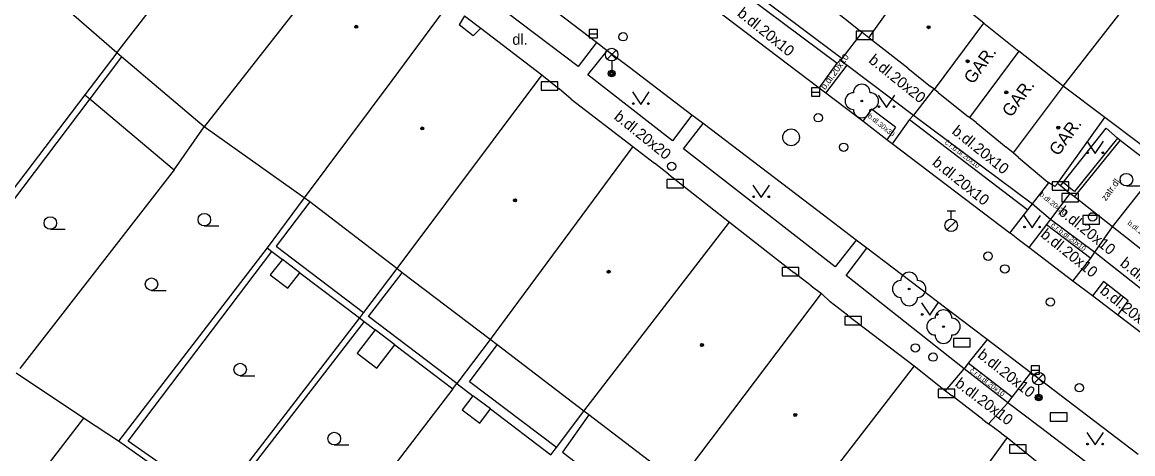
# Model space of a CAD drawing. Extents: x -595546 to -593986, y -1160845 to -1159202.
# Drawn here: x -595188.5 to -595122.2, y -1160653.2 to -1160627.4 of the extents above; entities that cross this region are included whole.
import ezdxf

# ---------------------------------------------------------------- set-up
doc = ezdxf.new("R2010")
doc.units = 0
for name, color, linetype in [('DOP - kresba z DSPS bez souradnic', 7, 'Continuous'), ('DOP - rozhrani ploch obecne', 7, 'Continuous'), ('Level 22', 7, 'Continuous'), ('Level 24', 7, 'Continuous'), ('Level 27', 7, 'Continuous'), ('Level 28', 7, 'Continuous'), ('Level 33', 7, 'Continuous'), ('Level 36', 7, 'Continuous'), ('Level 39', 7, 'Continuous'), ('TM - budovy zdene_ betonove - NP', 7, 'Continuous'), ('TM - budovy zdene_ betonove - VP', 7, 'Continuous'), ('TM - chodniky - VP', 7, 'Continuous'), ('TM - komunikace - VP', 7, 'Continuous'), ('TM - podezdivka plotu - VP', 7, 'Continuous'), ('TM - popis objektu', 7, 'Continuous'), ('TM - popis povrchu', 7, 'Continuous'), ('TM - rozhrani mezi zpev. plochami mezi sebou - VP', 7, 'Continuous'), ('TM - rozhrani ploch obecne - VP', 7, 'Continuous'), ('TM - vstup do budovy - zdene_ betonove', 7, 'Continuous'), ('TM - vstup do budovy - zdene_ betonove  - shora neviditelny', 7, 'Continuous'), ('TM - zed operna - VP', 7, 'Continuous')]:
    doc.layers.add(name, color=color, linetype=linetype)

msp = doc.modelspace()

# ---------------------------------------------------------------- linework, layer by layer
at = {"layer": 'DOP - kresba z DSPS bez souradnic'}
for points in [[(-595182.53, -1160629.5), (-595184.42, -1160632)], [(-595184.42, -1160632), (-595193.73, -1160644.32)], [(-595171.29, -1160638.17), (-595173.3, -1160640.82)], [(-595182.14, -1160652.47), (-595173.55, -1160641.13)], [(-595173.3, -1160640.82), (-595168.08, -1160644.78)], [(-595171.88, -1160642.4), (-595172.92, -1160641.61)], [(-595167.78, -1160645.02), (-595165.77, -1160642.4)], [(-595168.05, -1160645.31), (-595176.58, -1160656.37)], [(-595162.51, -1160649.02), (-595167.78, -1160645.02)], [(-595166.21, -1160646.71), (-595167.38, -1160645.82)], [(-595161.75, -1160648.91), (-595160.11, -1160646.71)], [(-595156.57, -1160652.85), (-595161.75, -1160648.91)], [(-595160.51, -1160650.54), (-595161.55, -1160649.75)], [(-595154.64, -1160650.9), (-595156.21, -1160653.12)], [(-595176.85, -1160656.17), (-595182.14, -1160652.47)], [(-595156.21, -1160653.12), (-595151.19, -1160656.94)]]:
    msp.add_lwpolyline(points, dxfattribs=at)
at = {"layer": 'DOP - rozhrani ploch obecne'}
for points in [[(-595182.82, -1160629.25), (-595184.73, -1160631.77)], [(-595184.73, -1160631.77), (-595194.24, -1160644.28)], [(-595184.73, -1160631.77), (-595184.42, -1160632)], [(-595184.42, -1160632), (-595179.38, -1160636.26)], [(-595179.38, -1160636.26), (-595177.6, -1160633.68)], [(-595179.38, -1160636.26), (-595188.61, -1160648.13)], [(-595171.62, -1160637.92), (-595173.84, -1160640.91)], [(-595173.84, -1160640.91), (-595182.72, -1160652.47)], [(-595173.84, -1160640.91), (-595173.55, -1160641.13)], [(-595173.55, -1160641.13), (-595172.92, -1160641.61)], [(-595172.92, -1160641.61), (-595173.65, -1160642.53)], [(-595173.65, -1160642.53), (-595172.61, -1160643.32)], [(-595172.61, -1160643.32), (-595171.88, -1160642.4)], [(-595171.88, -1160642.4), (-595168.33, -1160645.1)], [(-595166.1, -1160642.14), (-595168.08, -1160644.78)], [(-595168.33, -1160645.1), (-595176.85, -1160656.17)], [(-595168.08, -1160644.78), (-595168.33, -1160645.1)], [(-595168.33, -1160645.1), (-595168.05, -1160645.31)], [(-595168.05, -1160645.31), (-595167.38, -1160645.82)], [(-595167.38, -1160645.82), (-595168.47, -1160647.21)], [(-595167.29, -1160648.1), (-595166.21, -1160646.71)], [(-595166.21, -1160646.71), (-595162.76, -1160649.34)], [(-595160.53, -1160646.39), (-595162.51, -1160649.02)], [(-595168.47, -1160647.21), (-595167.29, -1160648.1)], [(-595184.8, -1160651.08), (-595188.82, -1160648.4)], [(-595162.76, -1160649.34), (-595171.1, -1160660.23)], [(-595162.76, -1160649.34), (-595162.51, -1160649.02)], [(-595162.51, -1160649.02), (-595161.55, -1160649.75)], [(-595161.55, -1160649.75), (-595162.19, -1160650.6)], [(-595162.19, -1160650.6), (-595161.15, -1160651.39)], [(-595161.15, -1160651.39), (-595160.51, -1160650.54)], [(-595160.51, -1160650.54), (-595156.91, -1160653.28)], [(-595156.57, -1160652.85), (-595154.93, -1160650.67)], [(-595184.8, -1160651.08), (-595190.54, -1160658.52)], [(-595182.72, -1160652.47), (-595184.8, -1160651.08)], [(-595178.89, -1160655.17), (-595182.72, -1160652.47)], [(-595156.91, -1160653.28), (-595156.57, -1160652.85)]]:
    msp.add_lwpolyline(points, dxfattribs=at)
at = {"layer": 'Level 22'}
for centre in [(-595138.34, -1160632.14), (-595135.51, -1160643.37), (-595133.46, -1160645.62)]:
    msp.add_circle(centre, 0.05, dxfattribs=at)
for centre, start, end in [((-595138.34, -1160631.64), 0, 180), ((-595138.84, -1160632.14), 90, 270), ((-595137.84, -1160632.14), 270, 90), ((-595138.34, -1160632.64), 180, 0), ((-595135.51, -1160642.87), 0, 180), ((-595136.01, -1160643.37), 90, 270), ((-595135.01, -1160643.37), 270, 90), ((-595135.51, -1160643.87), 180, 0), ((-595133.46, -1160645.12), 0, 180), ((-595133.96, -1160645.62), 90, 270), ((-595132.96, -1160645.62), 270, 90), ((-595133.46, -1160646.12), 180, 0)]:
    msp.add_arc(centre, 0.5, start, end, dxfattribs=at)
at = {"layer": 'Level 24'}
for points in [[(-595138.668, -1160628.469), (-595137.668, -1160628.469), (-595137.668, -1160627.969), (-595138.668, -1160627.969)], [(-595157.478, -1160631.489), (-595156.478, -1160631.489), (-595156.478, -1160630.989), (-595157.478, -1160630.989)], [(-595149.978, -1160637.319), (-595148.978, -1160637.319), (-595148.978, -1160636.819), (-595149.978, -1160636.819)], [(-595126.977, -1160637.458), (-595125.977, -1160637.458), (-595125.977, -1160636.958), (-595126.977, -1160636.958)], [(-595126.397, -1160638.168), (-595125.397, -1160638.168), (-595125.397, -1160637.668), (-595126.397, -1160637.668)], [(-595125.138, -1160639.489), (-595124.138, -1160639.489), (-595124.138, -1160638.989), (-595125.138, -1160638.989)], [(-595143.098, -1160642.579), (-595142.098, -1160642.579), (-595142.098, -1160642.079), (-595143.098, -1160642.079)], [(-595139.348, -1160645.509), (-595138.348, -1160645.509), (-595138.348, -1160645.009), (-595139.348, -1160645.009)], [(-595132.867, -1160646.828), (-595131.867, -1160646.828), (-595131.867, -1160646.328), (-595132.867, -1160646.328)], [(-595133.788, -1160649.849), (-595132.788, -1160649.849), (-595132.788, -1160649.349), (-595133.788, -1160649.349)], [(-595127.087, -1160651.278), (-595126.087, -1160651.278), (-595126.087, -1160650.778), (-595127.087, -1160650.778)], [(-595129.528, -1160653.179), (-595128.528, -1160653.179), (-595128.528, -1160652.679), (-595129.528, -1160652.679)]]:
    msp.add_lwpolyline(points, close=True, dxfattribs=at)
at = {"layer": 'Level 27'}
for p, q in [((-595154.61, -1160628.12), (-595154.11, -1160628.12)), ((-595141.35, -1160631.6), (-595140.85, -1160631.6)), ((-595128.22, -1160648.22), (-595127.72, -1160648.22))]:
    msp.add_line(p, q, dxfattribs=at)
for points in [[(-595154.61, -1160628.37), (-595154.11, -1160628.37), (-595154.11, -1160627.87), (-595154.61, -1160627.87)], [(-595141.35, -1160631.85), (-595140.85, -1160631.85), (-595140.85, -1160631.35), (-595141.35, -1160631.35)], [(-595128.22, -1160648.47), (-595127.72, -1160648.47), (-595127.72, -1160647.97), (-595128.22, -1160647.97)]]:
    msp.add_lwpolyline(points, close=True, dxfattribs=at)
msp.add_circle((-595142.56, -1160634.31), 0.5, dxfattribs=at)
at = {"layer": 'Level 28'}
for p, q in [((-595133.25, -1160638.695), (-595132.75, -1160638.695)), ((-595133, -1160639.195), (-595133, -1160638.695)), ((-595133.258, -1160639.842), (-595132.728, -1160639.312))]:
    msp.add_line(p, q, dxfattribs=at)
for centre, radius in [((-595152.59, -1160628.3), 0.25), ((-595140.94, -1160633.14), 0.25), ((-595139.42, -1160634.9), 0.25), ((-595149.69, -1160636.04), 0.25), ((-595133, -1160639.57), 0.375), ((-595124.56, -1160639.06), 0.25), ((-595130.8, -1160641.41), 0.25), ((-595129.8, -1160642.17), 0.25), ((-595127.08, -1160644.15), 0.25), ((-595135.14, -1160646.89), 0.25), ((-595134.08, -1160647.44), 0.25), ((-595125.35, -1160649.27), 0.25)]:
    msp.add_circle(centre, radius, dxfattribs=at)
at = {"layer": 'Level 33'}
for p, q in [((-595153.535, -1160629.63), (-595153.005, -1160629.1)), ((-595153.535, -1160629.1), (-595153.005, -1160629.63)), ((-595153.27, -1160629.74), (-595153.27, -1160630.49)), ((-595128.045, -1160648.99), (-595127.515, -1160648.46)), ((-595128.045, -1160648.46), (-595127.515, -1160648.99)), ((-595127.78, -1160649.1), (-595127.78, -1160649.85))]:
    msp.add_line(p, q, dxfattribs=at)
for centre, radius in [((-595153.27, -1160629.365), 0.375), ((-595153.27, -1160630.49), 0.2), ((-595153.27, -1160630.49), 0.145), ((-595153.27, -1160630.49), 0.0876), ((-595127.78, -1160648.725), 0.375), ((-595127.78, -1160649.85), 0.2), ((-595127.78, -1160649.85), 0.145), ((-595127.78, -1160649.85), 0.0876)]:
    msp.add_circle(centre, radius, dxfattribs=at)
at = {"layer": 'Level 36'}
for p, q in [((-595122.54, -1160637.215), (-595121.665, -1160637.215)), ((-595186.78, -1160639.805), (-595185.905, -1160639.805)), ((-595177.59, -1160639.605), (-595176.715, -1160639.605)), ((-595180.74, -1160643.455), (-595179.865, -1160643.455)), ((-595175.45, -1160648.555), (-595174.575, -1160648.555)), ((-595169.83, -1160652.685), (-595168.955, -1160652.685))]:
    msp.add_line(p, q, dxfattribs=at)
for points in [[(-595152.03, -1160631.59), (-595151.53, -1160632.34), (-595151.03, -1160631.59)], [(-595137.36, -1160631.78), (-595136.86, -1160632.53), (-595136.36, -1160631.78)], [(-595124.9, -1160634.53), (-595124.4, -1160635.28), (-595123.9, -1160634.53)], [(-595144.84, -1160637.16), (-595144.34, -1160637.91), (-595143.84, -1160637.16)], [(-595128.67, -1160638.97), (-595128.17, -1160639.72), (-595127.67, -1160638.97)], [(-595134.78, -1160644.19), (-595134.28, -1160644.94), (-595133.78, -1160644.19)], [(-595124.91, -1160651.94), (-595124.41, -1160652.69), (-595123.91, -1160651.94)]]:
    msp.add_lwpolyline(points, dxfattribs=at)
for centre, radius in [((-595151.98, -1160632.29), 0.05), ((-595151.081, -1160632.29), 0.05), ((-595137.31, -1160632.48), 0.05), ((-595136.411, -1160632.48), 0.05), ((-595124.85, -1160635.23), 0.05), ((-595123.951, -1160635.23), 0.05), ((-595122.54, -1160636.84), 0.375), ((-595144.79, -1160637.86), 0.05), ((-595143.891, -1160637.86), 0.05), ((-595186.78, -1160639.43), 0.375), ((-595177.59, -1160639.23), 0.375), ((-595128.62, -1160639.67), 0.05), ((-595127.721, -1160639.67), 0.05), ((-595180.74, -1160643.08), 0.375), ((-595134.73, -1160644.89), 0.05), ((-595133.831, -1160644.89), 0.05), ((-595175.45, -1160648.18), 0.375), ((-595169.83, -1160652.31), 0.375), ((-595124.86, -1160652.64), 0.05), ((-595123.961, -1160652.64), 0.05)]:
    msp.add_circle(centre, radius, dxfattribs=at)
at = {"layer": 'Level 39'}
for centre, radius in [((-595168.52, -1160627.7), 0.09), ((-595168.52, -1160627.7), 0.0398), ((-595134.35, -1160627.73), 0.09), ((-595134.35, -1160627.73), 0.0398), ((-595132.02, -1160629.76), 0.09), ((-595132.02, -1160629.76), 0.0398), ((-595129.71, -1160631.62), 0.09), ((-595129.71, -1160631.62), 0.0398), ((-595164.58, -1160633.78), 0.09), ((-595164.58, -1160633.78), 0.0398), ((-595126.61, -1160633.73), 0.09), ((-595126.61, -1160633.73), 0.0398), ((-595159.04, -1160638.07), 0.09), ((-595159.04, -1160638.07), 0.0398), ((-595153.45, -1160642.34), 0.09), ((-595153.45, -1160642.34), 0.0398), ((-595147.88, -1160646.72), 0.09), ((-595147.88, -1160646.72), 0.0398), ((-595142.31, -1160650.9), 0.09), ((-595142.31, -1160650.9), 0.0398)]:
    msp.add_circle(centre, radius, dxfattribs=at)
at = {"layer": 'TM - budovy zdene_ betonove - NP'}
for points in [[(-595137.92, -1160628.36), (-595135.04, -1160624.3)], [(-595162.05, -1160627.04), (-595162.38, -1160627.59)], [(-595161.54, -1160628.24), (-595161.08, -1160627.78)]]:
    msp.add_lwpolyline(points, dxfattribs=at)
at = {"layer": 'TM - budovy zdene_ betonove - VP'}
for points in [[(-595182.82, -1160629.25), (-595173.99, -1160617.88)], [(-595126.32, -1160631.26), (-595118.68, -1160621.44)], [(-595182.82, -1160629.25), (-595189.46, -1160623.47)], [(-595131.06, -1160627.48), (-595135.04, -1160624.3)], [(-595162.99, -1160626.32), (-595166.4, -1160630.91)], [(-595172.23, -1160626.83), (-595177.6, -1160633.68)], [(-595162.05, -1160627.04), (-595161.08, -1160627.78)], [(-595133.99, -1160631.46), (-595131.06, -1160627.48)], [(-595131.06, -1160627.48), (-595128.97, -1160629.15)], [(-595161.08, -1160627.78), (-595157.43, -1160630.57)], [(-595138.31, -1160628.05), (-595138.44, -1160627.95)], [(-595137.92, -1160628.36), (-595138.31, -1160628.05)], [(-595135.59, -1160630.18), (-595137.92, -1160628.36)], [(-595182.53, -1160629.5), (-595182.82, -1160629.25)], [(-595128.97, -1160629.15), (-595131.91, -1160633.13)], [(-595126.32, -1160631.26), (-595128.97, -1160629.15)], [(-595177.6, -1160633.68), (-595182.53, -1160629.5)], [(-595157.43, -1160630.57), (-595166.1, -1160642.14)], [(-595157.43, -1160630.57), (-595156.41, -1160631.42)], [(-595166.4, -1160630.91), (-595171.62, -1160637.92)], [(-595134.04, -1160631.42), (-595134.24, -1160631.27)], [(-595133.99, -1160631.46), (-595134.04, -1160631.42)], [(-595133.78, -1160631.63), (-595133.99, -1160631.46)], [(-595126.32, -1160631.26), (-595129.31, -1160635.23)], [(-595123.83, -1160633.13), (-595126.32, -1160631.26)], [(-595155.68, -1160632.02), (-595152, -1160634.86)], [(-595131.91, -1160633.13), (-595131.97, -1160633.08)], [(-595131.52, -1160633.43), (-595131.91, -1160633.13)], [(-595126.66, -1160637.06), (-595123.83, -1160633.13)], [(-595119.49, -1160636.39), (-595123.83, -1160633.13)], [(-595171.62, -1160637.92), (-595177.6, -1160633.68)], [(-595152, -1160634.86), (-595160.53, -1160646.39)], [(-595152, -1160634.86), (-595150.72, -1160635.86)], [(-595129.31, -1160635.23), (-595129.71, -1160634.9)], [(-595128.98, -1160635.51), (-595129.31, -1160635.23)], [(-595149.88, -1160636.51), (-595146.23, -1160639.37)], [(-595127.17, -1160637.02), (-595127.23, -1160636.98)], [(-595126.81, -1160637.25), (-595127.17, -1160637.02)], [(-595126.66, -1160637.06), (-595126.81, -1160637.25)], [(-595171.29, -1160638.17), (-595171.62, -1160637.92)], [(-595166.1, -1160642.14), (-595171.29, -1160638.17)], [(-595154.93, -1160650.67), (-595146.23, -1160639.37)], [(-595146.23, -1160639.37), (-595142.4, -1160642.38)], [(-595165.77, -1160642.4), (-595166.1, -1160642.14)], [(-595160.53, -1160646.39), (-595165.77, -1160642.4)], [(-595141.37, -1160643.18), (-595140.75, -1160643.64)], [(-595149.3, -1160654.98), (-595140.75, -1160643.64)], [(-595140.75, -1160643.64), (-595140.22, -1160644.13)], [(-595139.19, -1160644.93), (-595135.22, -1160647.97)], [(-595160.11, -1160646.71), (-595160.53, -1160646.39)], [(-595154.93, -1160650.67), (-595160.11, -1160646.71)], [(-595135.22, -1160647.97), (-595143.84, -1160659.15)], [(-595135.22, -1160647.97), (-595133.34, -1160649.45)], [(-595133.34, -1160649.45), (-595132.95, -1160649.76)], [(-595154.64, -1160650.9), (-595154.93, -1160650.67)], [(-595149.58, -1160654.76), (-595154.64, -1160650.9)], [(-595131.11, -1160651.17), (-595130.77, -1160651.43)], [(-595130.01, -1160651.98), (-595129.65, -1160652.25)], [(-595129.65, -1160652.25), (-595135.63, -1160660.49)], [(-595129.65, -1160652.25), (-595124.5, -1160656.42)]]:
    msp.add_lwpolyline(points, dxfattribs=at)
at = {"layer": 'TM - chodniky - VP'}
for points in [[(-595155.28, -1160630.08), (-595162.12, -1160624.88)], [(-595154.17, -1160628.64), (-595155.28, -1160630.08)], [(-595154.69, -1160630.57), (-595153.53, -1160629.13)], [(-595140.48, -1160631.67), (-595139.22, -1160630)], [(-595139.22, -1160630), (-595135.25, -1160632.98)], [(-595149.64, -1160634.51), (-595154.69, -1160630.57)], [(-595137.75, -1160632.62), (-595138.27, -1160633.35)], [(-595136.32, -1160633.71), (-595137.75, -1160632.62)], [(-595148.48, -1160632.98), (-595149.64, -1160634.51)], [(-595135.49, -1160633.25), (-595136.53, -1160634.69)], [(-595135.25, -1160632.98), (-595135.49, -1160633.25)], [(-595148.98, -1160634.99), (-595147.81, -1160633.49)], [(-595136.32, -1160633.71), (-595136.84, -1160634.45)], [(-595139.93, -1160642.05), (-595148.98, -1160634.99)], [(-595123.37, -1160639.66), (-595125.63, -1160637.86)], [(-595129.5, -1160640.03), (-595128.42, -1160638.64)], [(-595128.42, -1160638.64), (-595128.14, -1160638.29)], [(-595128.14, -1160638.29), (-595127.07, -1160639.19)], [(-595127.07, -1160639.19), (-595127.32, -1160639.51)], [(-595127.32, -1160639.51), (-595128.36, -1160640.89)], [(-595121.38, -1160641.24), (-595122.53, -1160640.31), (-595123.37, -1160639.66)], [(-595138.67, -1160640.45), (-595139.93, -1160642.05)], [(-595139.27, -1160642.57), (-595138.03, -1160640.94)], [(-595124.67, -1160641.52), (-595124.43, -1160641.18)], [(-595124.43, -1160641.18), (-595118.95, -1160645.49)], [(-595125.73, -1160642.9), (-595124.67, -1160641.52)], [(-595132.22, -1160648.14), (-595139.27, -1160642.57)], [(-595123.9, -1160642.92), (-595124.56, -1160643.77)], [(-595122.43, -1160644.07), (-595123.9, -1160642.92)], [(-595123.05, -1160644.93), (-595122.43, -1160644.07)], [(-595130.85, -1160646.39), (-595131.98, -1160647.81)], [(-595131.98, -1160647.81), (-595132.22, -1160648.14)], [(-595129.36, -1160649.84), (-595128.24, -1160648.39)], [(-595129.62, -1160650.17), (-595129.36, -1160649.84)], [(-595127.75, -1160651.58), (-595129.62, -1160650.17)], [(-595123.26, -1160655.01), (-595127.75, -1160651.58)]]:
    msp.add_lwpolyline(points, dxfattribs=at)
at = {"layer": 'TM - komunikace - VP'}
for points in [[(-595154.17, -1160628.64), (-595160.08, -1160624.13)], [(-595140.88, -1160631.37), (-595148.28, -1160625.73)], [(-595153.53, -1160629.13), (-595154.17, -1160628.64)], [(-595152.21, -1160630.14), (-595153.53, -1160629.13)], [(-595148.48, -1160632.98), (-595152.21, -1160630.14)], [(-595140.48, -1160631.67), (-595140.88, -1160631.37)], [(-595139.99, -1160632.04), (-595140.48, -1160631.67)], [(-595138.27, -1160633.35), (-595139.99, -1160632.04)], [(-595147.81, -1160633.49), (-595148.48, -1160632.98)], [(-595137.38, -1160634.03), (-595138.27, -1160633.35)], [(-595140.96, -1160638.71), (-595147.81, -1160633.49)], [(-595136.84, -1160634.45), (-595137.38, -1160634.03)], [(-595136.53, -1160634.69), (-595136.84, -1160634.45)], [(-595129.5, -1160640.03), (-595136.53, -1160634.69)], [(-595138.67, -1160640.45), (-595140.96, -1160638.71)], [(-595129.43, -1160640.08), (-595129.5, -1160640.03)], [(-595128.92, -1160640.47), (-595129.43, -1160640.08)], [(-595138.03, -1160640.94), (-595138.67, -1160640.45)], [(-595128.36, -1160640.89), (-595128.92, -1160640.47)], [(-595131.74, -1160645.72), (-595138.03, -1160640.94)], [(-595125.73, -1160642.9), (-595128.36, -1160640.89)], [(-595124.56, -1160643.77), (-595125.73, -1160642.9)], [(-595123.05, -1160644.93), (-595124.56, -1160643.77)], [(-595121.06, -1160646.44), (-595123.05, -1160644.93)], [(-595130.85, -1160646.39), (-595131.74, -1160645.72)], [(-595128.24, -1160648.39), (-595130.85, -1160646.39)], [(-595127.35, -1160649.06), (-595128.24, -1160648.39)], [(-595121.84, -1160653.26), (-595127.35, -1160649.06)]]:
    msp.add_lwpolyline(points, dxfattribs=at)
at = {"layer": 'TM - podezdivka plotu - VP'}
for points in [[(-595125.63, -1160637.86), (-595122.92, -1160634.5)], [(-595126.48, -1160637.21), (-595126.66, -1160637.06)], [(-595125.91, -1160637.67), (-595126.48, -1160637.21)], [(-595125.63, -1160637.86), (-595125.91, -1160637.67)]]:
    msp.add_lwpolyline(points, dxfattribs=at)
at = {"layer": 'TM - rozhrani mezi zpev. plochami mezi sebou - VP'}
for points in [[(-595146.98, -1160623.98), (-595139.51, -1160629.59)], [(-595147.23, -1160624.32), (-595139.8, -1160629.88)], [(-595139.51, -1160629.59), (-595138.31, -1160628.05)], [(-595140.88, -1160631.37), (-595139.8, -1160629.88)], [(-595139.8, -1160629.88), (-595139.62, -1160629.7)], [(-595139.62, -1160629.7), (-595139.51, -1160629.59)], [(-595139.62, -1160629.7), (-595139.22, -1160630)], [(-595134.04, -1160631.42), (-595135.25, -1160632.98)], [(-595135.49, -1160633.25), (-595128.42, -1160638.64)], [(-595135.25, -1160632.98), (-595128.14, -1160638.29)], [(-595123.37, -1160639.66), (-595120.66, -1160636.23)], [(-595128.14, -1160638.29), (-595127.17, -1160637.02)], [(-595125.91, -1160637.67), (-595127.07, -1160639.19)], [(-595127.07, -1160639.19), (-595124.43, -1160641.18)], [(-595127.32, -1160639.51), (-595124.67, -1160641.52)], [(-595124.43, -1160641.18), (-595123.37, -1160639.66)], [(-595129.36, -1160649.84), (-595131.98, -1160647.81)], [(-595133.34, -1160649.45), (-595132.22, -1160648.14)], [(-595129.62, -1160650.17), (-595132.22, -1160648.14)], [(-595130.77, -1160651.43), (-595129.62, -1160650.17)]]:
    msp.add_lwpolyline(points, dxfattribs=at)
at = {"layer": 'TM - rozhrani ploch obecne - VP'}
for points in [[(-595126.32, -1160637.01), (-595123.74, -1160633.76)], [(-595123.07, -1160634.36), (-595123.74, -1160633.76)], [(-595122.92, -1160634.5), (-595123.07, -1160634.36)], [(-595120.66, -1160636.23), (-595122.92, -1160634.5)], [(-595126.48, -1160637.21), (-595126.32, -1160637.01)]]:
    msp.add_lwpolyline(points, dxfattribs=at)
at = {"layer": 'TM - vstup do budovy - zdene_ betonove'}
for points in [[(-595140.28, -1160626.48), (-595138.44, -1160627.95)], [(-595135.59, -1160630.18), (-595134.24, -1160631.27)], [(-595155.68, -1160632.02), (-595156.41, -1160631.42)], [(-595133.78, -1160631.63), (-595131.97, -1160633.08)], [(-595131.52, -1160633.43), (-595129.71, -1160634.9)], [(-595149.88, -1160636.51), (-595150.72, -1160635.86)], [(-595128.98, -1160635.51), (-595127.23, -1160636.98)], [(-595141.37, -1160643.18), (-595142.4, -1160642.38)], [(-595139.19, -1160644.93), (-595140.22, -1160644.13)], [(-595131.11, -1160651.17), (-595132.95, -1160649.76)], [(-595130.01, -1160651.98), (-595130.77, -1160651.43)]]:
    msp.add_lwpolyline(points, dxfattribs=at)
at = {"layer": 'TM - vstup do budovy - zdene_ betonove  - shora neviditelny'}
msp.add_lwpolyline([(-595161.54, -1160628.24), (-595162.38, -1160627.59)], dxfattribs=at)
at = {"layer": 'TM - zed operna - VP'}
for points in [[(-595123.07, -1160634.36), (-595125.64, -1160637.54)], [(-595125.64, -1160637.54), (-595125.75, -1160637.46), (-595126.32, -1160637.01)]]:
    msp.add_lwpolyline(points, dxfattribs=at)

# ---------------------------------------------------------------- texts
at = {"layer": 'TM - popis objektu'}
for p in [(-595131.7, -1160631.18), (-595129.42, -1160633.16), (-595126.61, -1160635.47)]:
    msp.add_text('GAR.', height=0.75, rotation=54.14, dxfattribs=at).set_placement(p)
at = {"layer": 'TM - popis povrchu'}
for s, height, rotation, p in [('b.dl.20x10', 0.65, 321.14568, (-595145.82, -1160627)), ('b.dl.20x10', 0.4, 54, (-595140.53, -1160631.5)), ('b.dl.20x20', 0.65, 321.14568, (-595137.98, -1160629.79)), ('b.dl.20x20', 0.65, 321.14568, (-595153.18, -1160633.17)), ('b.dl.30x30', 0.3, 321.14568, (-595138.01, -1160633.09)), ('b.dl.20x10', 0.65, 321.14568, (-595133.01, -1160634.04)), ('č.r.b.dl.20x10', 0.3, 322.59388, (-595133.41, -1160634.67)), ('b.dl.20x10', 0.65, 321.14568, (-595134.18, -1160635.91)), ('zatr.dl.', 0.4, 53.4571, (-595123.77, -1160638.14)), ('b.dl.20x20', 0.3, 320.67246, (-595127.75, -1160637.78)), ('b.dl.20x10', 0.65, 321.14568, (-595126.65, -1160638.86)), ('č.r.b.dl.20x10', 0.3, 322.59388, (-595127.07, -1160639.61)), ('b.dl.10x10', 0.3, 320.96279, (-595122.5, -1160639.48)), ('b.dl.20x10', 0.65, 321.14568, (-595127.71, -1160640.21)), ('b.dl.20x20', 0.65, 321.14568, (-595122.97, -1160641.93)), ('b.dl.20x20', 0.65, 321.14568, (-595124.17, -1160643.57)), ('b.dl.20x10', 0.65, 321.57954, (-595131.47, -1160647.41)), ('b.dl.20x10', 0.65, 322.86796, (-595132.82, -1160649.13)), ('č.r.b.dl.20x10', 0.3, 322.26521, (-595131.92, -1160648.29))]:
    msp.add_text(s, height=height, rotation=rotation, dxfattribs=at).set_placement(p)
msp.add_text('dl.', height=0.65, dxfattribs=at).set_placement((-595159.2, -1160628.78))

doc.saveas('drawing.dxf')
